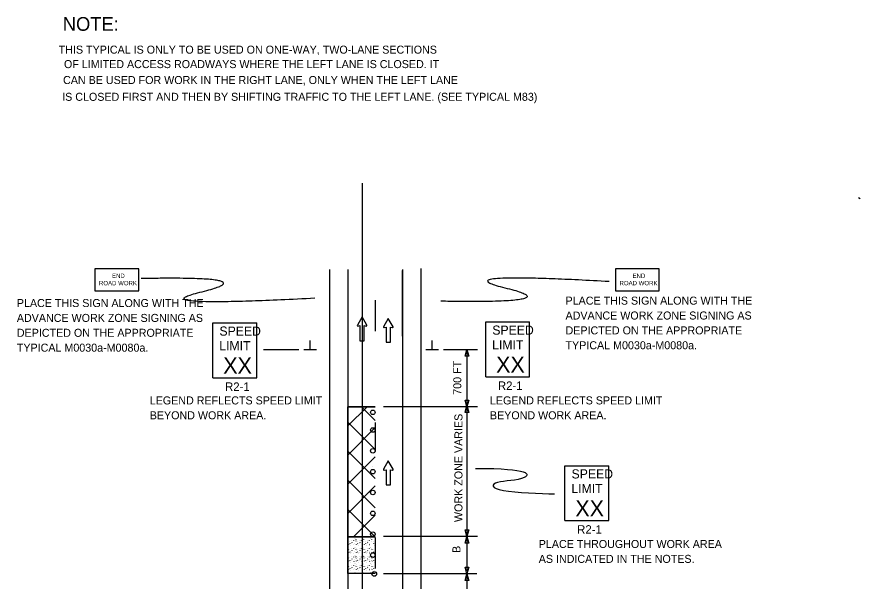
# Model space of a CAD drawing. Extents: x 15262 to 18126, y 1908 to 6555.
# Drawn here: x 15280 to 16017, y 2890 to 3383 of the extents above; entities that cross this region are included whole.
import ezdxf

# ---------------------------------------------------------------- set-up
doc = ezdxf.new("R2010")
doc.units = 0
for name, color, linetype in [('ALI_LEGAL_EX', 7, 'Continuous'), ('MT_SCRATCH_LEVEL_E', 7, 'Continuous'), ('PAVT_EDGE_EX', 7, 'Continuous'), ('TRAFFIC_SIGNS_PR', 7, 'Continuous'), ('TYPICAL_TEXT_DIMEN_EX', 7, 'Continuous'), ('TYPICAL_TEXT_DIMEN_PR', 7, 'Continuous')]:
    doc.layers.add(name, color=color, linetype=linetype)

msp = doc.modelspace()

# ---------------------------------------------------------------- linework, layer by layer
at = {"layer": 'ALI_LEGAL_EX'}
msp.add_line((15581.68, 3237.79), (15581.68, 2408.6), dxfattribs=at)
for points in [[(15593.04, 3135.48), (15593.04, 3108.47)], [(15593.04, 3028.73), (15593.04, 3003.32)], [(15593.04, 3003.32), (15593.04, 3003.32)], [(15590.55, 2989.82), (15590.55, 2989.82)], [(15593.01, 2927.95), (15593.01, 2900.94)]]:
    msp.add_lwpolyline(points, dxfattribs=at)
at = {"layer": 'MT_SCRATCH_LEVEL_E'}
for p, q in [((15581.51, 3120.83), (15577.39, 3113.59)), ((15585.65, 3113.59), (15581.51, 3120.83)), ((15577.88, 3112.91), (15579.65, 3113.22)), ((15579.65, 3113.22), (15579.65, 3099.97)), ((15583.4, 3099.97), (15583.4, 3113.22)), ((15583.4, 3113.22), (15585.17, 3112.91)), ((15604.48, 3119.56), (15600.37, 3112.32)), ((15608.63, 3112.32), (15604.48, 3119.56)), ((15600.85, 3111.64), (15602.63, 3111.95)), ((15602.63, 3111.95), (15602.63, 3098.7)), ((15606.37, 3098.7), (15606.37, 3111.95)), ((15606.37, 3111.95), (15608.15, 3111.64)), ((15579.65, 3099.97), (15583.4, 3099.97)), ((15602.63, 3098.7), (15606.37, 3098.7)), ((15604.48, 2994.95), (15600.37, 2987.71)), ((15608.63, 2987.71), (15604.48, 2994.95)), ((15600.85, 2987.02), (15602.63, 2987.34)), ((15602.63, 2987.34), (15602.63, 2974.08)), ((15606.37, 2974.08), (15606.37, 2987.34)), ((15606.37, 2987.34), (15608.15, 2987.02)), ((15602.63, 2974.08), (15606.37, 2974.08))]:
    msp.add_line(p, q, dxfattribs=at)
for centre, start, end in [((15577.8, 3113.37), 150.42484, 279.96381), ((15585.24, 3113.37), 260.03619, 29.77312), ((15600.78, 3112.1), 150.42484, 279.96381), ((15608.22, 3112.1), 260.03619, 29.77312), ((15600.78, 2987.48), 150.42484, 279.96381), ((15608.22, 2987.48), 260.03619, 29.77312)]:
    msp.add_arc(centre, 0.463, start, end, dxfattribs=at)
at = {"layer": 'PAVT_EDGE_EX'}
for p, q in [((15553, 3162.29), (15553, 2428.74)), ((15569, 3162.29), (15569, 2428.74)), ((15617, 3162.29), (15617, 2428.74)), ((15617, 3136.16), (15617, 3161.36)), ((15633, 3163.21), (15633, 2428.74)), ((15617, 3104.11), (15617, 3136.16)), ((15569.04, 2928.63), (15569.04, 3042.36)), ((15569.04, 3042.36), (15593.04, 3042.36)), ((15593.04, 3042.36), (15569.04, 3042.36)), ((15569.04, 3025.55), (15585.85, 3042.36)), ((15593.04, 3030.46), (15581.14, 3042.36)), ((15593.04, 3005), (15569.04, 3029)), ((15569.04, 3000.09), (15593.04, 3024.09)), ((15593.04, 2979.55), (15569.04, 3003.55)), ((15569.04, 2974.64), (15593.04, 2998.64)), ((15593.04, 2954.09), (15569.04, 2978.09)), ((15569.04, 2949.18), (15593.04, 2973.18)), ((15593.04, 2928.63), (15569.04, 2952.63)), ((15573.95, 2928.63), (15593.04, 2947.73)), ((15592.91, 2928.63), (15569.04, 2928.63)), ((15592.98, 2928.63), (15569.04, 2928.63)), ((15569.04, 2896.58), (15569.04, 2928.63)), ((15569.04, 2928.63), (15593.04, 2928.63)), ((15571.45, 2928.28), (15571.4, 2928.39)), ((15578.34, 2928.28), (15578.29, 2928.39)), ((15585.23, 2928.28), (15585.18, 2928.39)), ((15592.11, 2928.28), (15592.06, 2928.39)), ((15593.04, 2928.63), (15593.04, 2928.63)), ((15569.35, 2924.81), (15569.3, 2924.74)), ((15569.43, 2926.08), (15569.38, 2926.2)), ((15569.55, 2922.17), (15569.54, 2922.05)), ((15570.83, 2922.74), (15570.78, 2922.67)), ((15570.88, 2924.95), (15570.83, 2924.88)), ((15571.45, 2920.99), (15571.4, 2921.11)), ((15572.5, 2925.78), (15572.45, 2925.9)), ((15572.63, 2922.49), (15572.58, 2922.61)), ((15572.67, 2923.89), (15572.62, 2923.82)), ((15573.95, 2925.63), (15573.9, 2925.55)), ((15574.41, 2921.82), (15574.36, 2921.75)), ((15574.6, 2923.02), (15574.55, 2923.14)), ((15574.82, 2927.01), (15574.77, 2926.93)), ((15575.56, 2927.04), (15575.5, 2926.96)), ((15576.24, 2924.81), (15576.19, 2924.74)), ((15576.32, 2926.08), (15576.27, 2926.2)), ((15576.44, 2922.17), (15576.43, 2922.05)), ((15577.72, 2922.74), (15577.67, 2922.67)), ((15577.77, 2924.95), (15577.72, 2924.88)), ((15578.34, 2920.99), (15578.29, 2921.11)), ((15579.39, 2925.78), (15579.34, 2925.9)), ((15579.52, 2922.49), (15579.47, 2922.61)), ((15579.56, 2923.89), (15579.51, 2923.82)), ((15580.84, 2925.63), (15580.79, 2925.55)), ((15581.3, 2921.82), (15581.25, 2921.75)), ((15581.49, 2923.02), (15581.43, 2923.14)), ((15581.71, 2927.01), (15581.65, 2926.93)), ((15582.44, 2927.04), (15582.39, 2926.96)), ((15583.13, 2924.81), (15583.08, 2924.74)), ((15583.21, 2926.08), (15583.16, 2926.2)), ((15583.33, 2922.17), (15583.31, 2922.05)), ((15584.61, 2922.74), (15584.56, 2922.67)), ((15584.66, 2924.95), (15584.61, 2924.88)), ((15585.23, 2920.99), (15585.18, 2921.11)), ((15586.28, 2925.78), (15586.22, 2925.9)), ((15586.41, 2922.49), (15586.35, 2922.61)), ((15586.45, 2923.89), (15586.4, 2923.82)), ((15587.73, 2925.63), (15587.67, 2925.55)), ((15588.18, 2921.82), (15588.13, 2921.75)), ((15588.37, 2923.02), (15588.32, 2923.14)), ((15588.59, 2927.01), (15588.54, 2926.93)), ((15589.33, 2927.04), (15589.28, 2926.96)), ((15590.01, 2924.81), (15589.96, 2924.74)), ((15590.1, 2926.08), (15590.04, 2926.2)), ((15591.5, 2922.74), (15591.44, 2922.67)), ((15591.55, 2924.95), (15591.49, 2924.88)), ((15592.11, 2920.99), (15592.06, 2921.11)), ((15569.35, 2917.53), (15569.3, 2917.45)), ((15569.43, 2918.79), (15569.38, 2918.91)), ((15569.55, 2914.88), (15569.54, 2914.77)), ((15570.83, 2915.46), (15570.78, 2915.38)), ((15570.88, 2917.67), (15570.83, 2917.59)), ((15571.45, 2913.71), (15571.4, 2913.82)), ((15572.5, 2918.5), (15572.45, 2918.61)), ((15572.63, 2915.21), (15572.58, 2915.33)), ((15572.67, 2916.61), (15572.62, 2916.53)), ((15573.95, 2918.35), (15573.9, 2918.27)), ((15574.41, 2914.54), (15574.36, 2914.46)), ((15574.6, 2915.74), (15574.55, 2915.86)), ((15574.82, 2919.72), (15574.77, 2919.65)), ((15575.56, 2919.75), (15575.5, 2919.68)), ((15576.24, 2917.53), (15576.19, 2917.45)), ((15576.32, 2918.79), (15576.27, 2918.91)), ((15576.44, 2914.88), (15576.43, 2914.77)), ((15577.72, 2915.46), (15577.67, 2915.38)), ((15577.77, 2917.67), (15577.72, 2917.59)), ((15578.34, 2913.71), (15578.29, 2913.82)), ((15579.39, 2918.5), (15579.34, 2918.61)), ((15579.52, 2915.21), (15579.47, 2915.33)), ((15579.56, 2916.61), (15579.51, 2916.53)), ((15580.84, 2918.35), (15580.79, 2918.27)), ((15581.3, 2914.54), (15581.25, 2914.46)), ((15581.49, 2915.74), (15581.43, 2915.86)), ((15581.71, 2919.72), (15581.65, 2919.65)), ((15582.44, 2919.75), (15582.39, 2919.68)), ((15583.13, 2917.53), (15583.08, 2917.45)), ((15583.21, 2918.79), (15583.16, 2918.91)), ((15583.33, 2914.88), (15583.31, 2914.77)), ((15584.61, 2915.46), (15584.56, 2915.38)), ((15584.66, 2917.67), (15584.61, 2917.59)), ((15585.23, 2913.71), (15585.18, 2913.82)), ((15586.28, 2918.5), (15586.22, 2918.61)), ((15586.41, 2915.21), (15586.35, 2915.33)), ((15586.45, 2916.61), (15586.4, 2916.53)), ((15587.73, 2918.35), (15587.67, 2918.27)), ((15588.18, 2914.54), (15588.13, 2914.46)), ((15588.37, 2915.74), (15588.32, 2915.86)), ((15588.59, 2919.72), (15588.54, 2919.65)), ((15589.33, 2919.75), (15589.28, 2919.68)), ((15590.01, 2917.53), (15589.96, 2917.45)), ((15590.1, 2918.79), (15590.04, 2918.91)), ((15590.22, 2914.88), (15590.2, 2914.77)), ((15590.55, 2915.13), (15590.55, 2915.13)), ((15591.5, 2915.46), (15591.44, 2915.38)), ((15591.55, 2917.67), (15591.49, 2917.59)), ((15592.11, 2913.71), (15592.06, 2913.82)), ((15569.35, 2910.24), (15569.3, 2910.16)), ((15569.43, 2911.51), (15569.38, 2911.63)), ((15569.55, 2907.6), (15569.54, 2907.48)), ((15570.83, 2908.17), (15570.78, 2908.1)), ((15570.88, 2910.38), (15570.83, 2910.31)), ((15571.45, 2906.42), (15571.4, 2906.54)), ((15572.5, 2911.21), (15572.45, 2911.33)), ((15572.63, 2907.92), (15572.58, 2908.04)), ((15572.67, 2909.32), (15572.62, 2909.25)), ((15573.95, 2911.06), (15573.9, 2910.98)), ((15574.41, 2907.26), (15574.36, 2907.18)), ((15574.6, 2908.45), (15574.55, 2908.57)), ((15574.82, 2912.44), (15574.77, 2912.36)), ((15575.56, 2912.47), (15575.5, 2912.39)), ((15576.24, 2910.24), (15576.19, 2910.16)), ((15576.32, 2911.51), (15576.27, 2911.63)), ((15576.44, 2907.6), (15576.43, 2907.48)), ((15577.72, 2908.17), (15577.67, 2908.1)), ((15577.77, 2910.38), (15577.72, 2910.31)), ((15578.34, 2906.42), (15578.29, 2906.54)), ((15579.39, 2911.21), (15579.34, 2911.33)), ((15579.52, 2907.92), (15579.47, 2908.04)), ((15579.56, 2909.32), (15579.51, 2909.25)), ((15580.84, 2911.06), (15580.79, 2910.98)), ((15581.3, 2907.26), (15581.25, 2907.18)), ((15581.49, 2908.45), (15581.43, 2908.57)), ((15581.71, 2912.44), (15581.65, 2912.36)), ((15582.44, 2912.47), (15582.39, 2912.39)), ((15583.13, 2910.24), (15583.08, 2910.16)), ((15583.21, 2911.51), (15583.16, 2911.63)), ((15583.33, 2907.6), (15583.31, 2907.48)), ((15584.61, 2908.17), (15584.56, 2908.1)), ((15584.66, 2910.38), (15584.61, 2910.31)), ((15585.23, 2906.42), (15585.18, 2906.54)), ((15586.28, 2911.21), (15586.22, 2911.33)), ((15586.41, 2907.92), (15586.35, 2908.04)), ((15586.45, 2909.32), (15586.4, 2909.25)), ((15587.73, 2911.06), (15587.67, 2910.98)), ((15588.18, 2907.26), (15588.13, 2907.18)), ((15588.37, 2908.45), (15588.32, 2908.57)), ((15588.59, 2912.44), (15588.54, 2912.36)), ((15589.33, 2912.47), (15589.28, 2912.39)), ((15590.01, 2910.24), (15589.96, 2910.16)), ((15590.1, 2911.51), (15590.04, 2911.63)), ((15590.22, 2907.6), (15590.2, 2907.48)), ((15591.5, 2908.17), (15591.44, 2908.1)), ((15591.55, 2910.38), (15591.49, 2910.31)), ((15592.11, 2906.42), (15592.06, 2906.54)), ((15569.35, 2902.96), (15569.3, 2902.88)), ((15569.43, 2904.22), (15569.38, 2904.34)), ((15569.55, 2900.31), (15569.54, 2900.2)), ((15570.83, 2900.89), (15570.78, 2900.81)), ((15570.88, 2903.1), (15570.83, 2903.02)), ((15571.45, 2899.14), (15571.4, 2899.25)), ((15572.5, 2903.93), (15572.45, 2904.04)), ((15572.63, 2900.64), (15572.58, 2900.76)), ((15572.67, 2902.04), (15572.62, 2901.96)), ((15573.95, 2903.78), (15573.9, 2903.7)), ((15574.41, 2899.97), (15574.36, 2899.89)), ((15574.6, 2901.17), (15574.55, 2901.29)), ((15574.82, 2905.16), (15574.77, 2905.08)), ((15575.56, 2905.18), (15575.5, 2905.11)), ((15576.24, 2902.96), (15576.19, 2902.88)), ((15576.32, 2904.22), (15576.27, 2904.34)), ((15576.44, 2900.31), (15576.43, 2900.2)), ((15577.72, 2900.89), (15577.67, 2900.81)), ((15577.77, 2903.1), (15577.72, 2903.02)), ((15578.34, 2899.14), (15578.29, 2899.25)), ((15579.39, 2903.93), (15579.34, 2904.04)), ((15579.52, 2900.64), (15579.47, 2900.76)), ((15579.56, 2902.04), (15579.51, 2901.96)), ((15580.84, 2903.78), (15580.79, 2903.7)), ((15581.3, 2899.97), (15581.25, 2899.89)), ((15581.49, 2901.17), (15581.43, 2901.29)), ((15581.71, 2905.16), (15581.65, 2905.08)), ((15582.44, 2905.18), (15582.39, 2905.11)), ((15583.13, 2902.96), (15583.08, 2902.88)), ((15583.21, 2904.22), (15583.16, 2904.34)), ((15583.33, 2900.31), (15583.31, 2900.2)), ((15584.61, 2900.89), (15584.56, 2900.81)), ((15584.66, 2903.1), (15584.61, 2903.02)), ((15585.23, 2899.14), (15585.18, 2899.25)), ((15586.28, 2903.93), (15586.22, 2904.04)), ((15586.41, 2900.64), (15586.35, 2900.76)), ((15586.45, 2902.04), (15586.4, 2901.96)), ((15587.73, 2903.78), (15587.67, 2903.7)), ((15588.18, 2899.97), (15588.13, 2899.89)), ((15588.37, 2901.17), (15588.32, 2901.29)), ((15588.59, 2905.16), (15588.54, 2905.08)), ((15589.33, 2905.18), (15589.28, 2905.11)), ((15590.01, 2902.96), (15589.96, 2902.88)), ((15590.1, 2904.22), (15590.04, 2904.34)), ((15590.22, 2900.31), (15590.2, 2900.2)), ((15591.5, 2900.89), (15591.44, 2900.81)), ((15591.55, 2903.1), (15591.49, 2903.02)), ((15592.11, 2899.14), (15592.06, 2899.25)), ((15592.07, 2896.58), (15569.04, 2896.58)), ((15593.04, 2896.58), (15569.04, 2896.58)), ((15569.43, 2896.94), (15569.38, 2897.06)), ((15572.5, 2896.64), (15572.45, 2896.76)), ((15574.82, 2897.87), (15574.77, 2897.79)), ((15575.56, 2897.9), (15575.5, 2897.82)), ((15576.32, 2896.94), (15576.27, 2897.06)), ((15579.39, 2896.64), (15579.34, 2896.76)), ((15581.71, 2897.87), (15581.65, 2897.79)), ((15582.44, 2897.9), (15582.39, 2897.82)), ((15583.21, 2896.94), (15583.16, 2897.06)), ((15586.28, 2896.64), (15586.22, 2896.76)), ((15588.59, 2897.87), (15588.54, 2897.79)), ((15589.33, 2897.9), (15589.28, 2897.82)), ((15590.1, 2896.94), (15590.04, 2897.06)), ((15591.02, 2897.24), (15591.07, 2897.36)), ((15593.04, 2895.05), (15593.09, 2895.16)), ((15593.81, 2896.01), (15593.86, 2895.93))]:
    msp.add_line(p, q, dxfattribs=at)
at = {"layer": 'TRAFFIC_SIGNS_PR'}
for p, q in [((15451.02, 3115.61), (15489.43, 3115.61)), ((15451.02, 3067.61), (15451.02, 3115.61)), ((15489.43, 3067.61), (15489.43, 3115.61)), ((15689.66, 3116.46), (15728.06, 3116.46)), ((15689.66, 3068.46), (15689.66, 3116.46)), ((15728.06, 3068.46), (15728.06, 3116.46)), ((15689.66, 3068.46), (15728.06, 3068.46)), ((15451.02, 3067.61), (15489.43, 3067.61)), ((15758.97, 2990.82), (15797.37, 2990.82)), ((15758.97, 2942.82), (15758.97, 2990.82)), ((15797.37, 2942.82), (15797.37, 2990.82)), ((15758.97, 2942.82), (15797.37, 2942.82))]:
    msp.add_line(p, q, dxfattribs=at)
for points in [[(15347.83, 3143.76), (15386.23, 3143.76), (15386.23, 3162.96), (15347.83, 3162.96)], [(15803.06, 3143.76), (15841.46, 3143.76), (15841.46, 3162.96), (15803.06, 3162.96)]]:
    msp.add_lwpolyline(points, close=True, dxfattribs=at)
for centre in [(15590.9, 3037.49), (15590.94, 3022.02), (15590.94, 3003.81), (15590.94, 2985.6), (15590.94, 2967.38), (15590.94, 2949.17), (15590.94, 2930.95), (15590.94, 2912.74), (15592.19, 2896.27)]:
    msp.add_circle(centre, 2, dxfattribs=at)
for points in [[(15540.23, 3137.16), (15383.99, 3128.92), (15497.9, 3156.5), (15388.27, 3154.34)], [(15797.61, 3151.75), (15650.05, 3159.98), (15763.95, 3132.4), (15650.5, 3134.57)]]:
    msp.add_open_spline(points, degree=2, dxfattribs=at)
at = {"layer": 'TYPICAL_TEXT_DIMEN_PR'}
for p, q in [((16015.78, 3225.17), (16017.12, 3224.27)), ((15536.12, 3092.38), (15536.12, 3100.16)), ((15642.77, 3092.38), (15642.77, 3100.16)), ((15495.28, 3092.28), (15526.25, 3092.28)), ((15530.5, 3092.38), (15541.75, 3092.38)), ((15637.15, 3092.38), (15648.4, 3092.38)), ((15652.6, 3092.38), (15682.48, 3092.38)), ((15671.68, 3086.51), (15673.25, 3092.38)), ((15671.68, 3086.51), (15673.25, 3092.38)), ((15673.25, 3092.38), (15674.82, 3086.51)), ((15673.25, 3092.38), (15674.82, 3086.51)), ((15673.25, 3092.38), (15673.25, 3042.38)), ((15673.25, 3086.51), (15671.68, 3086.51)), ((15673.25, 3086.51), (15671.68, 3086.51)), ((15674.82, 3086.51), (15673.25, 3086.51)), ((15674.82, 3086.51), (15673.25, 3086.51)), ((15673.25, 3042.38), (15671.68, 3048.24)), ((15671.68, 3048.24), (15673.25, 3048.24)), ((15673.25, 3048.24), (15674.82, 3048.24)), ((15674.82, 3048.24), (15673.25, 3042.38)), ((15682.48, 3042.38), (15600.17, 3042.38)), ((15671.67, 3037.45), (15673.24, 3043.31)), ((15673.24, 3043.31), (15674.81, 3037.45)), ((15673.25, 3042.38), (15673.25, 2898.74)), ((15673.24, 3037.45), (15671.67, 3037.45)), ((15674.81, 3037.45), (15673.24, 3037.45)), ((15682.48, 2929.08), (15600.17, 2929.08)), ((15671.65, 2923.21), (15673.22, 2929.08)), ((15673.24, 2929.02), (15671.67, 2934.88)), ((15671.67, 2934.88), (15673.24, 2934.88)), ((15673.22, 2929.08), (15674.79, 2923.21)), ((15673.24, 2934.88), (15674.81, 2934.88)), ((15674.81, 2934.88), (15673.24, 2929.02)), ((15673.22, 2923.21), (15671.65, 2923.21)), ((15674.79, 2923.21), (15673.22, 2923.21)), ((15673.25, 2923.61), (15673.25, 2919.85)), ((15673.28, 2896.28), (15671.71, 2902.14)), ((15671.71, 2902.14), (15673.28, 2902.14)), ((15673.28, 2902.14), (15674.85, 2902.14)), ((15674.85, 2902.14), (15673.28, 2896.28)), ((15681.75, 2896.28), (15600.17, 2896.28)), ((15671.7, 2890.43), (15673.27, 2896.29)), ((15673.27, 2897.71), (15673.27, 2828.75)), ((15673.27, 2896.29), (15674.85, 2890.43)), ((15673.27, 2890.43), (15671.7, 2890.43)), ((15674.85, 2890.43), (15673.27, 2890.43))]:
    msp.add_line(p, q, dxfattribs=at)
msp.add_open_spline([(15680.65, 2988.49), (15729.12, 2988.49), (15729.12, 2977.74), (15694.2, 2977.74), (15694.2, 2968.02), (15737.81, 2966.53), (15749.94, 2966.27)], degree=3, dxfattribs=at)

# ---------------------------------------------------------------- texts
at = {"layer": 'TRAFFIC_SIGNS_PR'}
for s, height, p in [('END', 3.831, (15362.83, 3154.89)), ('END', 3.831, (15818.06, 3154.89)), ('ROAD WORK', 3.831, (15351.44, 3148.5)), ('ROAD WORK', 3.831, (15806.67, 3148.5)), ('PLACE THIS SIGN ALONG WITH THE', 7, (15279.61, 3129.48)), ('PLACE THIS SIGN ALONG WITH THE', 7, (15759.47, 3131.59)), ('ADVANCE WORK ZONE SIGNING AS', 7, (15279.61, 3116.48)), ('ADVANCE WORK ZONE SIGNING AS', 7, (15759.47, 3118.59)), ('SPEED', 8, (15456.79, 3104.47)), ('SPEED', 8, (15695.43, 3105.32)), ('DEPICTED ON THE APPROPRIATE', 7, (15759.47, 3105.59)), ('DEPICTED ON THE APPROPRIATE', 7, (15279.61, 3103.48)), ('TYPICAL M0030a-M0080a.', 7, (15279.61, 3090.48)), ('LIMIT', 8, (15456.63, 3091.67)), ('LIMIT', 8, (15695.27, 3092.52)), ('TYPICAL M0030a-M0080a.', 7, (15759.47, 3092.59)), ('XX', 14.031, (15460.14, 3071.37)), ('XX', 14.031, (15698.78, 3072.22)), ('R2-1', 7.44, (15461.7, 3056.17)), ('R2-1', 7.44, (15700.34, 3057.02)), ('LEGEND REFLECTS SPEED LIMIT', 7, (15395.84, 3044.39)), ('LEGEND REFLECTS SPEED LIMIT', 7, (15693.35, 3044.39)), ('BEYOND WORK AREA.', 7, (15395.84, 3031.39)), ('BEYOND WORK AREA.', 7, (15693.35, 3031.39)), ('SPEED', 8, (15764.73, 2979.68)), ('LIMIT', 8, (15764.57, 2966.88)), ('XX', 14.031, (15768.08, 2946.58)), ('R2-1', 7.44, (15769.64, 2931.38)), ('PLACE THROUGHOUT WORK AREA', 7, (15736.04, 2918.92)), ('AS INDICATED IN THE NOTES.', 7, (15736.04, 2905.92))]:
    msp.add_text(s, height=height, dxfattribs=at).set_placement(p)
at = {"layer": 'TYPICAL_TEXT_DIMEN_EX'}
msp.add_text('NOTE:', height=12, dxfattribs=at).set_placement((15319.77, 3370.89))
at = {"layer": 'TYPICAL_TEXT_DIMEN_PR'}
for s, p in [(' THIS TYPICAL IS ONLY TO BE USED ON ONE-WAY, TWO-LANE SECTIONS', (15313.61, 3350.94)), ('OF LIMITED ACCESS ROADWAYS WHERE THE LEFT LANE IS CLOSED. IT', (15320.82, 3338.3)), ('CAN BE USED FOR WORK IN THE RIGHT LANE, ONLY WHEN THE LEFT LANE ', (15320.04, 3324.38)), ('IS CLOSED FIRST AND THEN BY SHIFTING TRAFFIC TO THE LEFT LANE. (SEE TYPICAL M83)', (15319.26, 3309.72))]:
    msp.add_text(s, height=7, dxfattribs=at).set_placement(p)
for s, p in [('700 FT', (15668.29, 3052.79)), ('WORK ZONE VARIES', (15669.31, 2941.59)), ('B', (15667.56, 2914.59))]:
    msp.add_text(s, height=7, rotation=90, dxfattribs=at).set_placement(p)

doc.saveas('drawing.dxf')
